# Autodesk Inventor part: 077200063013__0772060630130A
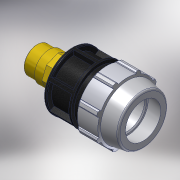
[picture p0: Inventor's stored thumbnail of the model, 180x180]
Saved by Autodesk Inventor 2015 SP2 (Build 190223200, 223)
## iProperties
Created: 2017-02
Part Number: 077200063013__0772060630130A
Material: PVC-Piping
Description: PLASSON MALE ADAPTOR INTEGRAL BRASS THREAD 63-1.1/4"
Document SubType Name: Modeling
Designer: KIM
Mass: 92.6774 g
Surface Area: 199.44 cm^2
Volume: 66.1981 cm^3
Density: 1.4 g/cm^3
Appearance: PTFE
Author: KIM
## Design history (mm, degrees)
derived "07720.ipt"
feature "Solid1::07720.ipt"
tag "TaggingFeature1"
body "Solid1"
other parameters: "d2" = 63, "d4" = 27.14286, "d5" = 27.14286, "d7" = 113, "d8" = 84.75, "d9" = 27.14286, "d11" = 5.42857, "d12" = 90.4, "d13" = 120 deg, "d14" = 88.2, "d15" = 10 deg, "d16" = 101.7, "d18" = 3.15, "d19" = 35 deg, "d20" = 17.5 deg, "d21" = 105.09, "d23" = 0, "d25" = 360 deg, "d27" = 2.26, "d34" = 5.65, "d36" = 0, "d42" = 38, "d43" = 3.39, "d46" = 1.89, "d49" = 123, "d53" = 1.26, "d55" = 360 deg, "d59" = 38, "d60" = 41.91, "d61" = 46.101, "d62" = 22, "d63" = 63.33333, "d64" = 29.337, "d66" = 23.3482, "d67" = 0, "d68" = 1.26, "d71" = 30 deg, "d72" = 37.719, "d_" = 63, "E_" = 113, "l_" = 123, "l_2" = 22, "R_" = 41.91, "d73" = 38.91366
